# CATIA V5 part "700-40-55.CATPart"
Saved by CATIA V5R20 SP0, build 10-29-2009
Part number: 700-40-55
Revision: ANY
Definition: UNKNOWN
Nomenclature: 700-40-55
Source: Unknown
Bounding box of the stored display mesh (mm): x -20 to 20, y 0 to 55, z -20 to 20
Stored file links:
  C:\Users\Utente\Desktop\IO LAVORO\3D X SITO CF\X SITO\700\700-40-55.CATPart
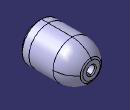
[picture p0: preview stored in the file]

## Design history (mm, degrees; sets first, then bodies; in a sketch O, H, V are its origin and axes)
Body1 "Rivoluzione1" (main body)
  Solid1: solid without history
